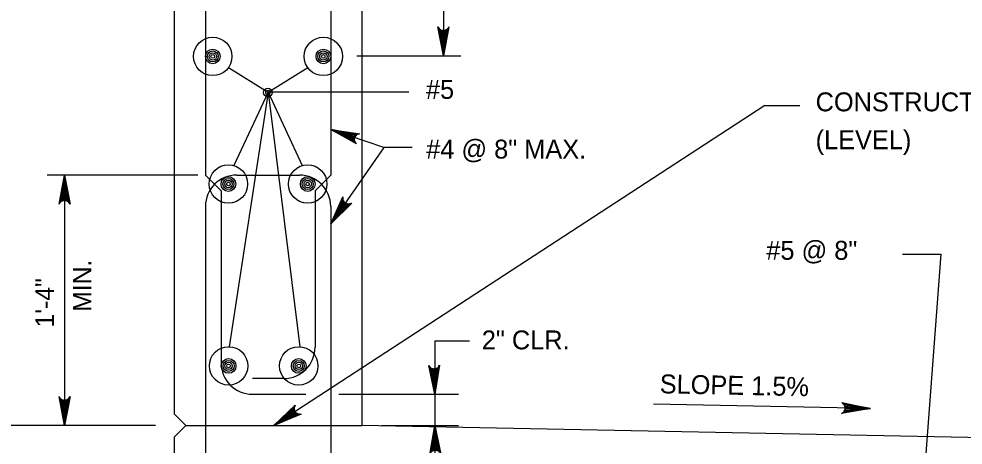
# Model space of a CAD drawing. Extents: x 638167 to 640248, y 296544 to 298920.
# Drawn here: x 638261.2 to 638414.4, y 296971.3 to 297040.5 of the extents above; entities that cross this region are included whole.
import ezdxf

# ---------------------------------------------------------------- set-up
doc = ezdxf.new("R2010")
doc.units = 0
for name, color, linetype in [('1', 7, 'Continuous'), ('50', 7, 'Continuous'), ('57', 7, 'Continuous')]:
    doc.layers.add(name, color=color, linetype=linetype)

# ---------------------------------------------------------------- blocks, each defined once
blk = doc.blocks.new('DIMDOT')
at = {"layer": '57'}
for radius in [2, 1]:
    blk.add_circle((0, 0), radius, dxfattribs=at)
blk = doc.blocks.new('BAR')
at = {"layer": '50'}
for radius in [2, 1.5, 1, 0.5]:
    blk.add_circle((0, 0), radius, dxfattribs=at)

msp = doc.modelspace()

# ---------------------------------------------------------------- linework, layer by layer
at = {"layer": '1'}
for p, q in [((638286.36, 297079.29), (638286.36, 296976.42)), ((638316.84, 297079.29), (638316.84, 296974.52)), ((638291.44, 297071.04), (638291.44, 297015.16)), ((638311.76, 297071.04), (638311.76, 297015.16)), ((638330.05, 297057.39), (638330.05, 297034.53)), ((638316, 297034.53), (638332.86, 297034.53)), ((638295.17, 297032.61), (638301.6, 297028.61)), ((638301.6, 297028.61), (638308.03, 297032.61)), ((638301.6, 297028.61), (638295.28, 296987.31)), ((638301.6, 297028.61), (638296.05, 297016.72)), ((638324.43, 297028.61), (638301.6, 297028.61)), ((638301.6, 297028.61), (638306.78, 296987.3)), ((638301.6, 297028.61), (638307.15, 297016.72)), ((638382.19, 297026.48), (638302.55, 296974.52)), ((638382.19, 297026.48), (638387.89, 297026.48)), ((638320.41, 297019.64), (638311.76, 297022.55)), ((638320.41, 297019.64), (638311.76, 297007.28)), ((638325, 297019.64), (638320.41, 297019.64)), ((638290.22, 297015.16), (638265.78, 297015.16)), ((638268.59, 297015.16), (638268.59, 296974.52)), ((638291.44, 297015.16), (638293.98, 297012.62)), ((638296.52, 297015.16), (638306.68, 297015.16)), ((638311.76, 297015.16), (638309.22, 297012.62)), ((638293.98, 297012.62), (638293.98, 296984.68)), ((638309.22, 297012.62), (638309.22, 296987.22)), ((638291.44, 297010.08), (638291.44, 296918.72)), ((638311.76, 297010.08), (638311.76, 296919.53)), ((638404.55, 297002.34), (638410.75, 297002.34)), ((638410.75, 297002.34), (638408.02, 296966.34)), ((638328.65, 296988.26), (638328.65, 296964.33)), ((638328.65, 296988.26), (638334.26, 296988.26)), ((638304.14, 296982.14), (638299.06, 296982.14)), ((638299.06, 296979.6), (638307.73, 296979.6)), ((638313.09, 296979.6), (638332.51, 296979.6)), ((638399.35, 296977.26), (638364.12, 296977.96)), ((638286.36, 296976.42), (638288.27, 296974.52)), ((638283.34, 296974.52), (638214.7, 296974.52)), ((638286.36, 296972.61), (638288.27, 296974.52)), ((638288.27, 296974.52), (638316.84, 296974.52)), ((638464.41, 296971.57), (638316.84, 296974.52)), ((638320, 296974.52), (638332.51, 296974.52)), ((638286.36, 296972.61), (638286.36, 296913.43))]:
    msp.add_line(p, q, dxfattribs=at)
for points in [[(638330.05, 297034.53), (638329.17, 297039.22), (638329.29, 297039.04), (638329.42, 297038.86), (638329.58, 297038.77), (638329.73, 297038.67), (638329.89, 297038.65), (638330.05, 297038.62), (638330.21, 297038.65), (638330.36, 297038.67), (638330.52, 297038.77), (638330.68, 297038.86), (638330.81, 297039.04), (638330.93, 297039.22), (638330.05, 297034.53), (638330.81, 297039.04), (638330.68, 297038.86), (638330.05, 297034.53), (638330.52, 297038.77), (638330.36, 297038.67), (638330.05, 297034.53), (638330.21, 297038.65), (638330.05, 297038.62), (638330.05, 297034.53), (638329.89, 297038.65), (638329.73, 297038.67), (638330.05, 297034.53), (638329.58, 297038.77), (638329.42, 297038.86), (638330.05, 297034.53), (638329.29, 297039.04)], [(638311.76, 297022.55), (638316.49, 297021.89), (638316.28, 297021.83), (638316.07, 297021.77), (638315.93, 297021.65), (638315.79, 297021.53), (638315.72, 297021.39), (638315.64, 297021.25), (638315.62, 297021.09), (638315.59, 297020.93), (638315.63, 297020.75), (638315.67, 297020.57), (638315.8, 297020.4), (638315.93, 297020.22), (638311.76, 297022.55), (638315.8, 297020.4), (638315.67, 297020.57), (638311.76, 297022.55), (638315.63, 297020.75), (638315.59, 297020.93), (638311.76, 297022.55), (638315.62, 297021.09), (638315.64, 297021.25), (638311.76, 297022.55), (638315.72, 297021.39), (638315.79, 297021.53), (638311.76, 297022.55), (638315.93, 297021.65), (638316.07, 297021.77), (638311.76, 297022.55), (638316.28, 297021.83)], [(638268.59, 297015.16), (638269.47, 297010.46), (638269.34, 297010.64), (638269.22, 297010.82), (638269.06, 297010.92), (638268.9, 297011.01), (638268.74, 297011.04), (638268.59, 297011.06), (638268.43, 297011.04), (638268.27, 297011.01), (638268.11, 297010.92), (638267.96, 297010.82), (638267.83, 297010.64), (638267.7, 297010.46), (638268.59, 297015.16), (638267.83, 297010.64), (638267.96, 297010.82), (638268.59, 297015.16), (638268.11, 297010.92), (638268.27, 297011.01), (638268.59, 297015.16), (638268.43, 297011.04), (638268.59, 297011.06), (638268.59, 297015.16), (638268.74, 297011.04), (638268.9, 297011.01), (638268.59, 297015.16), (638269.06, 297010.92), (638269.22, 297010.82), (638268.59, 297015.16), (638269.34, 297010.64)], [(638311.76, 297007.28), (638313.73, 297011.64), (638313.73, 297011.42), (638313.73, 297011.2), (638313.81, 297011.03), (638313.88, 297010.86), (638313.99, 297010.75), (638314.11, 297010.64), (638314.25, 297010.57), (638314.4, 297010.5), (638314.58, 297010.49), (638314.76, 297010.47), (638314.97, 297010.55), (638315.18, 297010.63), (638311.76, 297007.28), (638314.97, 297010.55), (638314.76, 297010.47), (638311.76, 297007.28), (638314.58, 297010.49), (638314.4, 297010.5), (638311.76, 297007.28), (638314.25, 297010.57), (638314.11, 297010.64), (638311.76, 297007.28), (638313.99, 297010.75), (638313.88, 297010.86), (638311.76, 297007.28), (638313.81, 297011.03), (638313.73, 297011.2), (638311.76, 297007.28), (638313.73, 297011.42)], [(638328.65, 296979.6), (638327.67, 296984.28), (638327.8, 296984.1), (638327.93, 296983.92), (638328.09, 296983.83), (638328.25, 296983.74), (638328.41, 296983.72), (638328.56, 296983.69), (638328.72, 296983.72), (638328.88, 296983.75), (638329.03, 296983.85), (638329.19, 296983.95), (638329.31, 296984.13), (638329.43, 296984.31), (638328.65, 296979.6), (638329.31, 296984.13), (638329.19, 296983.95), (638328.65, 296979.6), (638329.03, 296983.85), (638328.88, 296983.75), (638328.65, 296979.6), (638328.72, 296983.72), (638328.56, 296983.69), (638328.65, 296979.6), (638328.41, 296983.72), (638328.25, 296983.74), (638328.65, 296979.6), (638328.09, 296983.83), (638327.93, 296983.92), (638328.65, 296979.6), (638327.8, 296984.1)], [(638268.59, 296974.52), (638267.7, 296979.22), (638267.83, 296979.03), (638267.96, 296978.85), (638268.11, 296978.76), (638268.27, 296978.67), (638268.43, 296978.64), (638268.59, 296978.61), (638268.74, 296978.64), (638268.9, 296978.67), (638269.06, 296978.76), (638269.22, 296978.85), (638269.34, 296979.03), (638269.47, 296979.22), (638268.59, 296974.52), (638269.34, 296979.03), (638269.22, 296978.85), (638268.59, 296974.52), (638269.06, 296978.76), (638268.9, 296978.67), (638268.59, 296974.52), (638268.74, 296978.64), (638268.59, 296978.61), (638268.59, 296974.52), (638268.43, 296978.64), (638268.27, 296978.67), (638268.59, 296974.52), (638268.11, 296978.76), (638267.96, 296978.85), (638268.59, 296974.52), (638267.83, 296979.03)], [(638399.35, 296977.26), (638394.63, 296976.47), (638394.81, 296976.59), (638395, 296976.71), (638395.09, 296976.87), (638395.19, 296977.02), (638395.22, 296977.18), (638395.25, 296977.34), (638395.23, 296977.5), (638395.2, 296977.65), (638395.11, 296977.81), (638395.02, 296977.97), (638394.84, 296978.1), (638394.67, 296978.23), (638399.35, 296977.26), (638394.84, 296978.1), (638395.02, 296977.97), (638399.35, 296977.26), (638395.11, 296977.81), (638395.2, 296977.65), (638399.35, 296977.26), (638395.23, 296977.5), (638395.25, 296977.34), (638399.35, 296977.26), (638395.22, 296977.18), (638395.19, 296977.02), (638399.35, 296977.26), (638395.09, 296976.87), (638395, 296976.71), (638399.35, 296977.26), (638394.81, 296976.59)], [(638302.55, 296974.52), (638306.01, 296977.82), (638305.92, 296977.62), (638305.84, 296977.41), (638305.85, 296977.23), (638305.86, 296977.05), (638305.92, 296976.9), (638305.98, 296976.76), (638306.09, 296976.64), (638306.2, 296976.52), (638306.36, 296976.44), (638306.53, 296976.36), (638306.75, 296976.35), (638306.97, 296976.35), (638302.55, 296974.52), (638306.75, 296976.35), (638306.53, 296976.36), (638302.55, 296974.52), (638306.36, 296976.44), (638306.2, 296976.52), (638302.55, 296974.52), (638306.09, 296976.64), (638305.98, 296976.76), (638302.55, 296974.52), (638305.92, 296976.9), (638305.86, 296977.05), (638302.55, 296974.52), (638305.85, 296977.23), (638305.84, 296977.41), (638302.55, 296974.52), (638305.92, 296977.62)], [(638327.86, 296969.8), (638328.65, 296974.52), (638327.98, 296969.99)], [(638328.1, 296970.17), (638328.65, 296974.52), (638328.26, 296970.27)], [(638328.41, 296970.36), (638328.65, 296974.52), (638328.57, 296970.39)], [(638328.65, 296974.52), (638329.62, 296969.84)], [(638328.73, 296970.42), (638328.65, 296974.52), (638328.88, 296970.4)], [(638329.04, 296970.38), (638328.65, 296974.52), (638329.2, 296970.29)], [(638329.36, 296970.2), (638328.65, 296974.52), (638329.49, 296970.02)]]:
    msp.add_lwpolyline(points, dxfattribs=at)
for centre in [(638292.63, 297034.43), (638310.57, 297034.43), (638295.17, 297013.72), (638308.03, 297013.72), (638295.2, 296984.19), (638306.58, 296984.19)]:
    msp.add_circle(centre, 3.12, dxfattribs=at)
for centre, start, end in [((638296.52, 297010.08), 90, 180), ((638306.68, 297010.08), 0, 90), ((638304.14, 296987.22), 270, 0), ((638299.06, 296984.68), 180, 270)]:
    msp.add_arc(centre, 5.08, start, end, dxfattribs=at)

# ---------------------------------------------------------------- block references
at = {"layer": '1', "xscale": 0.5953136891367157, "yscale": 0.5953136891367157, "rotation": -90.00000000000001}
for p in [(638292.63, 297034.43), (638310.57, 297034.43), (638295.17, 297013.72), (638308.03, 297013.72), (638295.2, 296984.19), (638306.58, 296984.19)]:
    msp.add_blockref('BAR', p, dxfattribs=at)
at = {"layer": '1', "xscale": 0.349999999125, "yscale": 0.349999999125}
msp.add_blockref('DIMDOT', (638301.57, 297028.58), dxfattribs=at)

# ---------------------------------------------------------------- texts
at = {"layer": '1'}
for s, p in [('#5', (638327.22, 297027.54)), ('CONSTRUCTION JOINT', (638390.44, 297025.52)), ('(LEVEL)', (638390.44, 297019.37)), ('#4 @ 8" MAX.', (638327.26, 297017.85)), ('#5 @ 8"', (638382.44, 297001.42)), ('2" CLR.', (638336.28, 296986.87))]:
    msp.add_text(s, height=3.072, dxfattribs=at).set_placement(p)
for s, height, rotation, p in [('MIN.', 3, 90, (638272.93, 296992.98)), ('1\'-4"', 3, 90, (638266.86, 296990.44)), ('SLOPE 1.5%', 3.072, 358.8542, (638365.12, 296979.75))]:
    msp.add_text(s, height=height, rotation=rotation, dxfattribs=at).set_placement(p)

doc.saveas('drawing.dxf')
